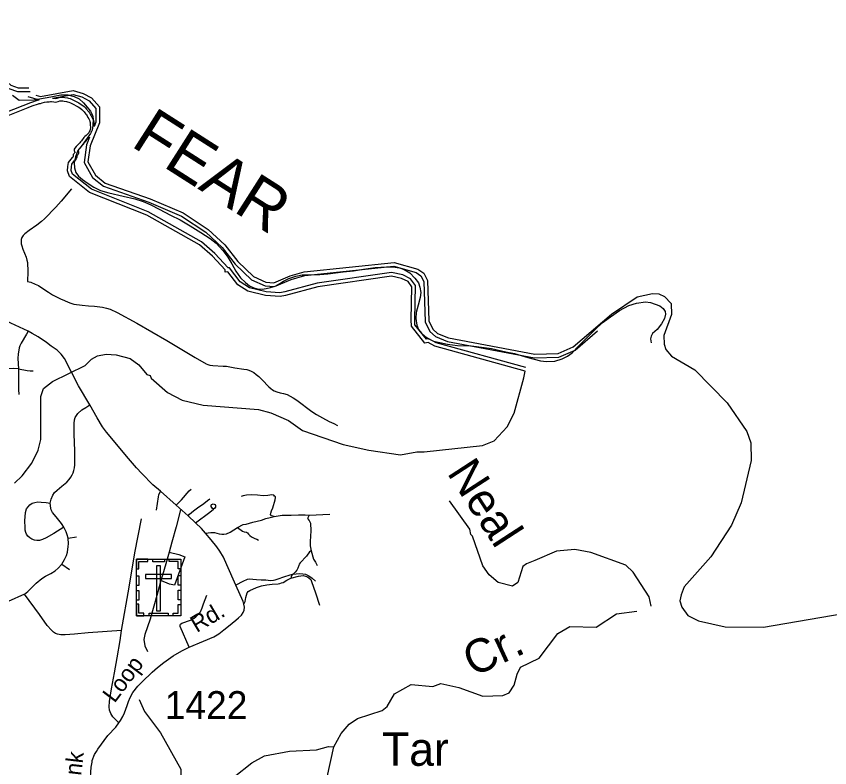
# Model space of a CAD drawing. Extents: x 2225501 to 2309677, y 165449 to 227696.
# Drawn here: x 2266364 to 2280990, y 212881 to 226385 of the extents above; entities that cross this region are included whole.
import ezdxf

# ---------------------------------------------------------------- set-up
doc = ezdxf.new("R2010")
doc.units = 0
for name, color, linetype in [('E_RDY_CMT_EOP', 7, 'Continuous'), ('MARK ENDS WORD SYMBOL CELL', 7, 'Continuous'), ('Old_Level_18', 7, 'Continuous'), ('Old_Level_3', 7, 'Continuous'), ('Old_Level_33', 7, 'Continuous'), ('Old_Level_51', 7, 'Continuous'), ('Old_Level_63', 7, 'Continuous'), ('P_HYD_Drop_Inlet_Grate_2_Wide_Slot_and_Sag_Grates_840_22_48_Dia_Apron_CELL', 7, 'Continuous'), ('P_RDY_Concrete_Monolithic_Island', 7, 'Continuous'), ('Prop Mkg Solid Yellow Edge Line', 7, 'Continuous'), ('Prop Support', 7, 'Continuous'), ('Scratch_Level_1', 7, 'Continuous'), ('Typical Terminator CELL', 7, 'Continuous')]:
    doc.layers.add(name, color=color, linetype=linetype)

msp = doc.modelspace()

# ---------------------------------------------------------------- linework, layer by layer
at = {"layer": 'Old_Level_18'}
msp.add_line((2266181, 224660), (2266624, 224833), dxfattribs=at)
for points in [[(2264160, 226130), (2264747, 226318), (2264972, 226320), (2265278, 226258), (2265413, 226170), (2265504, 226083), (2266053, 225251), (2266229, 225090), (2266387, 225032), (2266613, 225036)], [(2267017, 224915), (2267387, 224982), (2267540, 224939), (2267674, 224866), (2267793, 224730), (2267795, 224482), (2267762, 224402)], [(2266572, 224942), (2266775, 224881)], [(2266624, 224833), (2266748, 224876), (2266775, 224881)], [(2267017, 224915), (2267050, 224911), (2267067, 224908), (2267099, 224914), (2267133, 224927), (2267155, 224930), (2267184, 224931), (2267210, 224930), (2267239, 224925), (2267284, 224917), (2267304, 224912), (2267332, 224905), (2267367, 224891), (2267393, 224879), (2267420, 224866), (2267487, 224829), (2267515, 224811), (2267545, 224791), (2267585, 224762)], [(2267585, 224762), (2267610, 224738), (2267623, 224724), (2267637, 224707), (2267647, 224693), (2267666, 224669), (2267681, 224650), (2267694, 224629), (2267710, 224599), (2267725, 224573), (2267739, 224545), (2267750, 224514), (2267756, 224482), (2267757, 224449), (2267759, 224426), (2267762, 224402)], [(2267683, 224213), (2267662, 224195), (2267644, 224176), (2267629, 224162), (2267618, 224150), (2267601, 224127), (2267586, 224109), (2267572, 224090), (2267553, 224068), (2267530, 224044), (2267510, 224023), (2267493, 224001), (2267475, 223980), (2267478, 223968), (2267482, 223947), (2267481, 223917), (2267470, 223896), (2267461, 223882), (2267453, 223873), (2267450, 223849), (2267442, 223826), (2267418, 223793), (2267413, 223792)], [(2267683, 224213), (2267626, 224077), (2267583, 223755), (2267736, 223486), (2267931, 223330), (2268750, 223045)], [(2267376, 223547), (2267354, 223616), (2267357, 223679), (2267365, 223729), (2267413, 223792)], [(2271192, 221434), (2271102, 221418), (2270857, 221432), (2270556, 221507), (2270391, 221610), (2270197, 221865), (2270176, 221862), (2269937, 222122), (2269694, 222333), (2268738, 222872), (2267714, 223277), (2267376, 223547)], [(2268750, 223045), (2269335, 222795), (2269771, 222503), (2270065, 222232), (2270301, 221933), (2270591, 221651), (2270837, 221542), (2271006, 221527), (2271308, 221657), (2271555, 221725), (2273151, 221895), (2273556, 221782), (2273641, 221723), (2273695, 221618), (2273719, 220895), (2273798, 220721), (2273901, 220631), (2274117, 220541), (2275683, 220246), (2276119, 220258), (2276414, 220386), (2276816, 220733)], [(2275527, 220075), (2273913, 220516), (2273783, 220588), (2273741, 220582), (2273533, 220841), (2273532, 220932), (2273544, 221547), (2273454, 221668), (2273315, 221736), (2273112, 221780), (2271774, 221590), (2271192, 221434)]]:
    msp.add_lwpolyline(points, dxfattribs=at)
at = {"layer": 'Old_Level_3'}
for p, q in [((2271632, 217419), (2272001, 217440)), ((2267295, 217004), (2267445, 217028)), ((2267182, 216540), (2267324, 216444)), ((2266514, 215997), (2266219, 215866))]:
    msp.add_line(p, q, dxfattribs=at)
for points in [[(2267357, 223286), (2267174, 223062), (2267077, 222957), (2266872, 222746), (2266818, 222700), (2266733, 222633), (2266596, 222537), (2266519, 222474), (2266487, 222444), (2266466, 222412), (2266454, 222375), (2266451, 222337), (2266453, 222293), (2266462, 222257), (2266482, 222200), (2266540, 222054), (2266555, 222005), (2266563, 221961), (2266569, 221797), (2266568, 221617)], [(2266568, 221617), (2266624, 221604), (2266704, 221572), (2266762, 221545), (2266825, 221508), (2266946, 221425), (2267016, 221382), (2267157, 221310), (2267232, 221275), (2267296, 221246), (2267347, 221227), (2267401, 221213), (2267549, 221193), (2267661, 221180), (2267771, 221173), (2267913, 221155), (2267984, 221140), (2268050, 221121), (2268178, 221061), (2268529, 220869), (2269069, 220561), (2269310, 220414), (2269583, 220251), (2269778, 220142), (2269807, 220129), (2269846, 220117), (2269900, 220110), (2270084, 220100), (2270145, 220095), (2270204, 220086), (2270293, 220066), (2270457, 220046), (2270509, 220037), (2270547, 220025), (2270589, 220008), (2270634, 219982), (2270680, 219949), (2270727, 219910), (2270785, 219854), (2270903, 219726), (2270939, 219694), (2270969, 219673), (2271004, 219655), (2271052, 219638), (2271110, 219620), (2271170, 219607), (2271232, 219586), (2271291, 219561), (2271345, 219531), (2271407, 219487), (2271678, 219285), (2271760, 219231), (2271870, 219166), (2271988, 219103), (2272071, 219064), (2272140, 219029)], [(2266578, 220728), (2266545, 220675), (2266454, 220511), (2266431, 220462), (2266419, 220427), (2266410, 220386), (2266399, 220316), (2266395, 220235), (2266403, 220052)], [(2266403, 220052), (2266316, 220054), (2266035, 220047), (2265992, 220053), (2265958, 220059), (2265907, 220081)], [(2266403, 220052), (2266557, 220021), (2266613, 220011), (2266670, 220012)], [(2266403, 220052), (2266404, 219926), (2266406, 219677), (2266408, 219590)], [(2266975, 217635), (2266991, 217710), (2267021, 217781), (2267054, 217827), (2267097, 217868), (2267182, 217942), (2267274, 218012), (2267314, 218058), (2267343, 218101), (2267371, 218147), (2267386, 218183), (2267398, 218225), (2267410, 218270), (2267416, 218326), (2267419, 218428), (2267419, 218578), (2267403, 218878), (2267406, 219066), (2267411, 219130), (2267423, 219176), (2267444, 219212), (2267468, 219249), (2267541, 219312), (2267612, 219357), (2267689, 219403)], [(2268958, 217850), (2268922, 217787), (2268918, 217749), (2268878, 217508)], [(2269237, 217598), (2269337, 217698), (2269473, 217855), (2269510, 217886)], [(2267217, 217204), (2267038, 217088), (2266899, 217010), (2266834, 216984), (2266782, 216967), (2266735, 216964), (2266690, 216973), (2266642, 216989), (2266605, 217012), (2266574, 217042), (2266550, 217076), (2266533, 217105), (2266522, 217148), (2266522, 217199), (2266516, 217315), (2266530, 217469), (2266550, 217532), (2266576, 217572), (2266609, 217605), (2266651, 217635), (2266698, 217647), (2266751, 217657), (2266812, 217653), (2266899, 217646), (2266975, 217635)], [(2269455, 217406), (2269478, 217435), (2269550, 217499), (2269622, 217551), (2269739, 217629), (2269801, 217681), (2269845, 217715)], [(2271000, 217397), (2270951, 217406), (2270937, 217429), (2270939, 217457), (2270956, 217496), (2270976, 217552), (2271022, 217693), (2271028, 217739), (2271024, 217751), (2271010, 217763), (2270994, 217777), (2270961, 217783), (2270888, 217775), (2270806, 217765), (2270699, 217777), (2270593, 217784), (2270506, 217779), (2270441, 217769), (2270410, 217755)], [(2267217, 217204), (2267179, 217267), (2267106, 217358), (2267049, 217423), (2267017, 217467), (2266993, 217516), (2266984, 217548), (2266975, 217635)], [(2269314, 217515), (2269240, 217211), (2269161, 216934), (2269116, 216753)], [(2269587, 217279), (2269844, 217472), (2269910, 217528)], [(2268256, 215348), (2268391, 216127), (2268498, 216745), (2268615, 217352)], [(2270344, 217196), (2270441, 217254), (2270498, 217259), (2270617, 217293), (2270772, 217331), (2270849, 217362), (2270928, 217377), (2271000, 217397)], [(2271000, 217397), (2271143, 217418), (2271307, 217422), (2271440, 217428), (2271557, 217428), (2271632, 217419)], [(2271632, 217419), (2271601, 217361), (2271632, 217326), (2271653, 217274), (2271658, 217136), (2271648, 216948), (2271650, 216871), (2271664, 216779)], [(2267295, 217004), (2267278, 217064), (2267259, 217122), (2267246, 217155), (2267217, 217204)], [(2269769, 217095), (2269861, 217108), (2269930, 217106), (2270013, 217085), (2270059, 217076), (2270094, 217076), (2270142, 217086), (2270210, 217116), (2270344, 217196)], [(2270344, 217196), (2270430, 217132), (2270462, 217120), (2270504, 217114), (2270521, 217101), (2270537, 217080), (2270561, 217052), (2270595, 217029), (2270653, 216998), (2270692, 216988), (2270719, 216973)], [(2267182, 216540), (2267233, 216625), (2267267, 216692), (2267285, 216753), (2267299, 216857), (2267302, 216907), (2267295, 217004)], [(2271664, 216779), (2271638, 216760), (2271581, 216684), (2271469, 216560), (2271453, 216540), (2271443, 216516), (2271425, 216465), (2271407, 216432), (2271380, 216393), (2271343, 216360)], [(2271664, 216779), (2271707, 216626), (2271745, 216575), (2271775, 216515)], [(2269116, 216753), (2269065, 216589), (2269009, 216403), (2268963, 216245)], [(2269116, 216753), (2269286, 216714), (2269393, 216669), (2269212, 216160), (2269122, 216177), (2268963, 216245)], [(2266514, 215997), (2266574, 216050), (2266723, 216196), (2266822, 216280), (2266889, 216322), (2266984, 216374), (2267061, 216421), (2267117, 216468), (2267182, 216540)], [(2271343, 216360), (2271186, 216314), (2271050, 216265), (2271016, 216253), (2270989, 216245), (2270940, 216242), (2270895, 216246), (2270852, 216250), (2270768, 216250), (2270682, 216259), (2270553, 216272), (2270513, 216262), (2270440, 216227), (2270312, 216164)], [(2271343, 216360), (2271315, 216332), (2271304, 216312), (2271298, 216288)], [(2271298, 216288), (2271440, 216322), (2271523, 216334), (2271566, 216325), (2271601, 216310), (2271629, 216286), (2271658, 216262), (2271674, 216230), (2271745, 216025), (2271814, 215802)], [(2271343, 216360), (2271448, 216373), (2271517, 216367), (2271565, 216359), (2271626, 216332), (2271682, 216288), (2271747, 216232)], [(2268963, 216245), (2268912, 216041), (2268862, 215866), (2268839, 215787)], [(2270457, 215819), (2270477, 215867), (2270490, 215940), (2270517, 216024), (2270536, 216047), (2270566, 216064), (2270686, 216119), (2270774, 216152), (2270868, 216170), (2270963, 216180), (2271073, 216187), (2271104, 216192), (2271135, 216202), (2271161, 216211), (2271229, 216250), (2271298, 216288)], [(2268256, 215348), (2267654, 215305), (2267410, 215281), (2267243, 215267), (2267166, 215267), (2267108, 215278), (2267068, 215294), (2267032, 215318), (2266995, 215350), (2266921, 215438), (2266784, 215633), (2266514, 215997)], [(2269473, 215046), (2269312, 215420), (2269310, 215443), (2269317, 215462), (2269340, 215478), (2269497, 215534), (2269562, 215571), (2269595, 215593), (2269624, 215625), (2269675, 215683), (2269705, 215754), (2269733, 215826), (2269788, 215979)], [(2268839, 215787), (2268771, 215549), (2268675, 215272), (2268658, 215187), (2268675, 215074), (2268726, 214967)], [(2268210, 213687), (2268101, 213798), (2268064, 213855), (2268040, 213913), (2268033, 213973), (2268043, 214071), (2268079, 214300), (2268128, 214584), (2268176, 214855), (2268234, 215166), (2268256, 215348)]]:
    msp.add_lwpolyline(points, dxfattribs=at)
msp.add_lwpolyline([(2269910, 217528), (2269885, 217548), (2269866, 217574), (2269866, 217591), (2269876, 217609), (2269890, 217620), (2269905, 217624), (2269925, 217620), (2269938, 217609), (2269946, 217596), (2269948, 217578), (2269946, 217562), (2269936, 217546)], close=True, dxfattribs=at)
at = {"layer": 'Old_Level_33'}
for points in [[(2268210, 213687), (2268238, 213730), (2268282, 213802), (2268311, 213870), (2268358, 213998), (2268382, 214071), (2268411, 214142), (2268462, 214234), (2268552, 214346), (2268625, 214426), (2268805, 214597), (2268901, 214681), (2269018, 214769), (2269183, 214889), (2269340, 214984), (2269473, 215046), (2269733, 215158), (2269914, 215233), (2270007, 215288), (2270098, 215356), (2270179, 215423), (2270312, 215530), (2270361, 215572), (2270413, 215623), (2270442, 215670), (2270461, 215711), (2270465, 215764), (2270457, 215819), (2270444, 215870), (2270312, 216164), (2270150, 216527), (2270090, 216667), (2270022, 216772), (2269970, 216849), (2269870, 216979), (2269769, 217095), (2269692, 217178), (2269587, 217279), (2269455, 217406), (2269237, 217598), (2268958, 217850), (2268821, 217966), (2268619, 218171), (2268524, 218273), (2268381, 218440), (2267988, 218909), (2267915, 219009), (2267818, 219166), (2267689, 219403), (2267482, 219745), (2267233, 220233), (2267171, 220312), (2267097, 220385), (2266992, 220459), (2266908, 220520), (2266755, 220623), (2266649, 220687), (2266578, 220728), (2266027, 220979)], [(2267691, 212617), (2267711, 212893), (2267727, 212980), (2267731, 213013), (2267772, 213116), (2267804, 213171), (2267831, 213215), (2268013, 213461), (2268152, 213609), (2268210, 213687)]]:
    msp.add_lwpolyline(points, dxfattribs=at)
at = {"layer": 'Old_Level_51'}
for points in [[(2266295, 224967), (2266419, 224875), (2266678, 224881), (2266986, 224937), (2267166, 224972), (2267290, 224972), (2267408, 224946), (2267493, 224899), (2267573, 224828), (2267697, 224680), (2267736, 224609), (2267744, 224544), (2267739, 224420), (2267727, 224337), (2267700, 224281), (2267550, 224071), (2267473, 223971), (2267431, 223858), (2267408, 223752)], [(2267408, 223752), (2267411, 223663), (2267434, 223578), (2267485, 223510), (2267552, 223454), (2267638, 223392), (2267756, 223315), (2267877, 223256), (2268028, 223214), (2268285, 223155), (2268497, 223102), (2268645, 223055), (2268784, 222996), (2268932, 222916), (2269138, 222810), (2269310, 222730), (2269493, 222617), (2269682, 222499), (2269850, 222393), (2269956, 222307), (2270077, 222174), (2270169, 222059), (2270240, 221935), (2270311, 221805), (2270396, 221687), (2270485, 221598), (2270559, 221542), (2270635, 221504), (2270694, 221486), (2270783, 221480), (2270860, 221492), (2270937, 221509), (2271019, 221536), (2271105, 221580), (2271170, 221625), (2271267, 221672), (2271391, 221716), (2271507, 221737), (2271660, 221740), (2271823, 221743), (2271964, 221758), (2272242, 221793), (2272428, 221811), (2272608, 221840), (2272815, 221870), (2273018, 221885), (2273134, 221882), (2273255, 221867), (2273340, 221834), (2273438, 221772), (2273532, 221681), (2273594, 221592), (2273618, 221518), (2273639, 221421), (2273624, 221329), (2273591, 221193), (2273553, 221063), (2273547, 220954), (2273565, 220833), (2273597, 220759), (2273653, 220691), (2273712, 220635), (2273783, 220591), (2273866, 220549), (2273981, 220523), (2274120, 220493), (2274300, 220466), (2274542, 220461), (2274776, 220431), (2274911, 220413), (2275168, 220354), (2275322, 220322), (2275564, 220251), (2275791, 220195), (2275898, 220180), (2276045, 220189), (2276178, 220227), (2276273, 220280), (2276361, 220339), (2276476, 220458), (2276648, 220632), (2276810, 220791), (2276919, 220889), (2277049, 220986), (2277209, 221099), (2277380, 221187), (2277513, 221229), (2277675, 221255), (2277767, 221244), (2277853, 221211), (2277935, 221179), (2277997, 221134), (2278030, 221081), (2278036, 221034), (2278021, 220954), (2277968, 220856), (2277888, 220759), (2277805, 220682), (2277782, 220638), (2277770, 220591), (2277779, 220517)]]:
    msp.add_lwpolyline(points, dxfattribs=at)
at = {"layer": 'Old_Level_63'}
for p, q in [((2266191, 224593), (2266578, 224745)), ((2266578, 224745), (2266650, 224773))]:
    msp.add_line(p, q, dxfattribs=at)
for points in [[(2264141, 226193), (2264737, 226384), (2264978, 226385), (2265304, 226320), (2265454, 226222), (2265555, 226125), (2266104, 225294), (2266264, 225147), (2266398, 225098), (2266589, 225101)], [(2266716, 224967), (2266799, 224943), (2267390, 225049), (2267565, 225000), (2267716, 224918), (2267859, 224755), (2267861, 224469), (2267690, 224059), (2267651, 223768), (2267787, 223529), (2267963, 223388), (2268774, 223106)], [(2266650, 224773), (2266765, 224812), (2266778, 224815), (2266800, 224818), (2266830, 224830), (2266870, 224844), (2266912, 224846), (2266934, 224846), (2266958, 224850), (2266978, 224852), (2267000, 224851), (2267040, 224846), (2267068, 224841), (2267118, 224851), (2267150, 224863), (2267160, 224865), (2267184, 224865), (2267204, 224865), (2267228, 224861), (2267270, 224853), (2267288, 224848), (2267312, 224842), (2267342, 224830), (2267366, 224820), (2267390, 224808), (2267453, 224772), (2267479, 224756), (2267507, 224737), (2267543, 224711)], [(2267543, 224711), (2267563, 224693), (2267573, 224681), (2267585, 224667), (2267595, 224653), (2267615, 224629), (2267627, 224613), (2267637, 224597), (2267653, 224567), (2267667, 224542), (2267678, 224518), (2267686, 224497), (2267690, 224475), (2267692, 224444), (2267694, 224420), (2267696, 224398), (2267696, 224371), (2267694, 224355), (2267685, 224329), (2267676, 224307), (2267666, 224291), (2267653, 224275), (2267633, 224257), (2267618, 224243), (2267597, 224223), (2267581, 224207), (2267567, 224191), (2267549, 224167), (2267535, 224149), (2267521, 224131), (2267505, 224112), (2267483, 224089), (2267461, 224066), (2267442, 224043), (2267420, 224017), (2267408, 223996), (2267404, 223984), (2267404, 223976), (2267408, 223968), (2267412, 223962), (2267414, 223954), (2267416, 223942), (2267416, 223934), (2267414, 223930), (2267408, 223922), (2267402, 223914), (2267394, 223908), (2267388, 223904), (2267386, 223898), (2267388, 223892), (2267388, 223880), (2267386, 223864), (2267384, 223857), (2267379, 223851), (2267374, 223849)], [(2267319, 223508), (2267288, 223607), (2267291, 223686), (2267303, 223755), (2267374, 223849)], [(2271206, 221370), (2271106, 221352), (2270847, 221367), (2270530, 221446), (2270346, 221561), (2270169, 221794), (2270119, 221785), (2270118, 221828), (2269891, 222075), (2269656, 222279), (2268710, 222813), (2267681, 223220), (2267319, 223508)], [(2268774, 223106), (2269367, 222852), (2269812, 222555), (2270114, 222277), (2270350, 221977), (2270628, 221706), (2270854, 221607), (2270995, 221594), (2271286, 221720), (2271543, 221790), (2273157, 221962), (2273584, 221842), (2273692, 221768), (2273760, 221635), (2273784, 220910), (2273852, 220761), (2273936, 220687), (2274136, 220604), (2275688, 220312), (2276105, 220323), (2276379, 220443), (2277064, 221033), (2277528, 221345), (2277802, 221405), (2277919, 221400), (2278019, 221352), (2278137, 221225), (2278147, 221028), (2278009, 220650), (2278011, 220493), (2278045, 220394), (2278146, 220277), (2278565, 220033), (2279145, 219438), (2279500, 218922), (2279569, 218718), (2279580, 218399), (2279395, 217639), (2279224, 217238), (2278855, 216668), (2278376, 216130), (2278320, 215990), (2278296, 215879), (2278330, 215764), (2278440, 215614), (2278632, 215518), (2279108, 215414), (2279799, 215404), (2281230, 215651)], [(2275517, 220010), (2273888, 220455), (2273771, 220520), (2273713, 220511), (2273468, 220818), (2273467, 220932), (2273478, 221526), (2273411, 221616), (2273293, 221674), (2273110, 221713), (2271787, 221526), (2271206, 221370)]]:
    msp.add_lwpolyline(points, dxfattribs=at)
at = {"layer": 'Prop Mkg Solid Yellow Edge Line'}
for points in [[(2268524, 216628), (2269320, 216628), (2269320, 215610), (2268524, 215610)], [(2268524, 216455), (2268569, 216455), (2268569, 216584), (2268731, 216584), (2268731, 216628), (2268524, 216628)], [(2268820, 216628), (2269027, 216628), (2269027, 216583), (2268820, 216583)], [(2269320, 216455), (2269275, 216455), (2269275, 216584), (2269113, 216584), (2269113, 216628), (2269320, 216628)], [(2268960, 216511), (2268885, 216511), (2268885, 215700), (2268960, 215700)], [(2268524, 216158), (2268524, 216332), (2268569, 216332), (2268569, 216158)], [(2268687, 216356), (2268687, 216281), (2269158, 216281), (2269158, 216356)], [(2269275, 216163), (2269275, 216336), (2269320, 216336), (2269320, 216163)], [(2268524, 215890), (2268524, 216063), (2268569, 216063), (2268569, 215890)], [(2269275, 215899), (2269275, 216072), (2269320, 216072), (2269320, 215899)], [(2268656, 215610), (2268656, 215656), (2268568, 215656), (2268568, 215818), (2268523, 215818), (2268523, 215610)], [(2269187, 215610), (2269187, 215656), (2269275, 215656), (2269275, 215817), (2269320, 215817), (2269320, 215610)], [(2268753, 215656), (2269093, 215656), (2269093, 215610), (2268753, 215610)]]:
    msp.add_lwpolyline(points, close=True, dxfattribs=at)
at = {"layer": 'Prop Support'}
msp.add_lwpolyline([(2268575, 214107), (2268668, 213892), (2268955, 213509), (2269320, 212856), (2269315, 212430), (2269491, 212357), (2269997, 212561), (2270279, 212716), (2270601, 212969), (2270825, 213096), (2271274, 213176), (2271765, 213202), (2271981, 213263), (2272073, 213255)], dxfattribs=at)
at = {"layer": 'Typical Terminator CELL'}
for points in [[(2266331, 217992), (2266471, 218127), (2266644, 218353), (2266759, 218587), (2266807, 218780), (2266808, 219554), (2266856, 219697), (2267014, 219822), (2267602, 220112), (2267718, 220221), (2267826, 220282), (2267983, 220315), (2268159, 220301), (2268409, 220237), (2268568, 220119), (2268712, 219946), (2268770, 219932), (2268787, 219882), (2269081, 219627), (2269349, 219488), (2269725, 219398), (2270717, 219317), (2270942, 219260), (2271260, 219122), (2271512, 218940), (2272239, 218690), (2272706, 218586), (2273273, 218506), (2273564, 218559), (2273697, 218560), (2274746, 218671), (2274954, 218755), (2275193, 219009), (2275315, 219250), (2275493, 219886), (2275517, 220010)], [(2277780, 215784), (2277745, 215949), (2277458, 216397), (2277323, 216521), (2276697, 216750), (2276405, 216805), (2276080, 216775), (2275690, 216605), (2275541, 216546), (2275474, 216495), (2275385, 216211), (2275286, 216144), (2275027, 216208), (2274868, 216349), (2274750, 216506), (2274570, 217044), (2274536, 217071), (2274519, 217170), (2274156, 217675)], [(2272073, 213255), (2272204, 213498), (2272352, 213666), (2272501, 213768), (2272941, 213907), (2273032, 213981), (2273164, 214208), (2273462, 214376), (2273854, 214339), (2273995, 214392), (2274320, 214320), (2274755, 214164), (2275113, 214176), (2275229, 214227), (2275319, 214363), (2275368, 214562), (2275433, 214688), (2275765, 214849), (2276102, 215292), (2276317, 215419), (2276792, 215406), (2277157, 215645), (2277523, 215697)], [(2266822, 208260), (2266946, 208343), (2267177, 208588), (2267349, 208922), (2267506, 209100), (2268176, 209503), (2268409, 209564), (2268951, 209478), (2269293, 209498), (2269740, 209735), (2269951, 210381), (2270050, 210464), (2270491, 210508), (2270657, 210577), (2270880, 210730), (2271246, 210857), (2271353, 210960), (2271402, 211044), (2271530, 211678), (2271835, 212040), (2271953, 212713), (2272073, 213255)]]:
    msp.add_lwpolyline(points, dxfattribs=at)

# ---------------------------------------------------------------- texts
at = {"layer": 'E_RDY_CMT_EOP'}
msp.add_text('1422', height=500, dxfattribs=at).set_placement((2269033, 213757))
at = {"layer": 'MARK ENDS WORD SYMBOL CELL'}
for s, rotation, p in [('Rd.', 30.6559, (2269608, 215301)), ('Loop', 53.0433, (2268131, 214030)), ('Bank', 83.2952, (2267473, 212243))]:
    msp.add_text(s, height=300, rotation=rotation, dxfattribs=at).set_placement(p)
at = {"layer": 'P_HYD_Drop_Inlet_Grate_2_Wide_Slot_and_Sag_Grates_840_22_48_Dia_Apron_CELL'}
msp.add_text('FEAR', height=840, rotation=327.4747, dxfattribs=at).set_placement((2268405, 224064))
at = {"layer": 'P_RDY_Concrete_Monolithic_Island'}
msp.add_text(' Tar', height=600, dxfattribs=at).set_placement((2272716, 212915))
at = {"layer": 'Scratch_Level_1'}
for s, rotation, p in [('Neal', 302.9765, (2274098, 218179)), ('Cr.', 24.7573, (2274575, 214506))]:
    msp.add_text(s, height=600, rotation=rotation, dxfattribs=at).set_placement(p)

doc.saveas('drawing.dxf')
